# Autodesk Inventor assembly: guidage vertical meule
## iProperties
Shininess: 64.0
Length Units: 11269
Angle Units: 11279
Time Units: 11290
Mass Units: 11283
Length Display Precision: 3
Angle Display Precision: 2
Compacted: True
Created: 2004-12
Part Number: guidage vertical meule
Document SubType Name: Assembly
Designer: LEGERET Philippe
Density: 0.0
Volumn: 0.0
Area: 0.0
PropertySet Name: Model Information
Control State: 0
Master: False
Checked Out: False
Author: LEGERET Philippe
